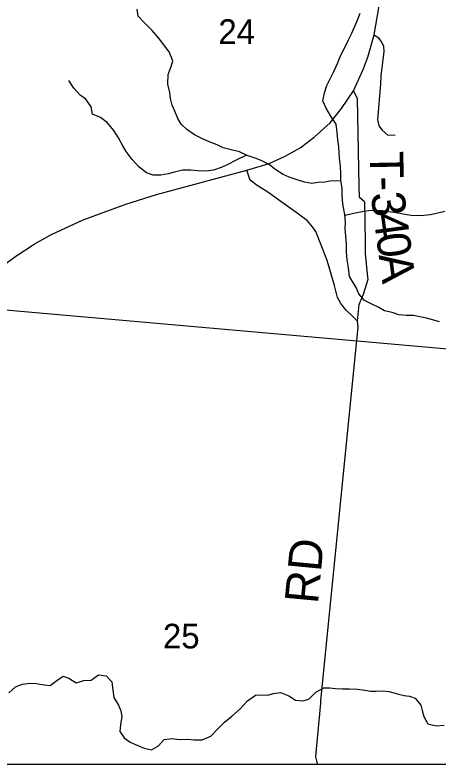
# Model space of a CAD drawing. Extents: x 0 to 42, y 0 to 22.
# Drawn here: x 4.427 to 4.786, y 14.1 to 14.736 of the extents above; entities that cross this region are included whole.
import ezdxf

# ---------------------------------------------------------------- set-up
doc = ezdxf.new("R2010")
doc.units = 0
for name, color, linetype in [('GM_X_Major_River', 7, 'Continuous'), ('GM_X_Minor_River', 7, 'Continuous'), ('GM_X_Section', 7, 'Continuous'), ('GM_X_Section_Text', 7, 'Continuous'), ('GM_X_State_Route', 7, 'Continuous'), ('GM_X_Township_Road', 7, 'Continuous'), ('GM_X_Township_Road_Text', 7, 'Continuous'), ('GM_X_Unincorporated', 7, 'Continuous'), ('SH_Cut_Line', 7, 'Continuous'), ('SH_Data', 7, 'Continuous')]:
    doc.layers.add(name, color=color, linetype=linetype)

msp = doc.modelspace()

# ---------------------------------------------------------------- linework, layer by layer
at = {"layer": 'GM_X_Major_River'}
msp.add_lwpolyline([(4.42158, 14.16044), (4.42726, 14.16538), (4.43333, 14.16766), (4.43996, 14.16861), (4.44489, 14.16842), (4.4519, 14.1671), (4.45683, 14.16653), (4.46251, 14.1709), (4.46782, 14.17451), (4.47256, 14.17281), (4.47882, 14.16883), (4.48545, 14.17092), (4.49151, 14.17111), (4.49777, 14.17567), (4.5044, 14.17473), (4.50914, 14.1698), (4.5099, 14.16278), (4.51086, 14.15652), (4.51484, 14.14988), (4.51674, 14.14514), (4.5175, 14.14039), (4.51656, 14.13337), (4.51599, 14.12749), (4.51959, 14.12218), (4.52471, 14.11858), (4.53116, 14.11574), (4.53647, 14.11346), (4.54272, 14.11214), (4.54879, 14.11556), (4.55352, 14.12069), (4.56035, 14.12164), (4.56622, 14.12069), (4.57324, 14.12108), (4.57892, 14.12051), (4.58575, 14.12052), (4.59314, 14.12375), (4.59882, 14.12945), (4.60469, 14.13552), (4.61075, 14.14027), (4.61795, 14.14691), (4.62439, 14.15375), (4.63121, 14.1585), (4.63633, 14.15869), (4.64145, 14.15831), (4.64619, 14.15984), (4.65244, 14.16079), (4.65946, 14.15776), (4.66514, 14.15416), (4.67121, 14.15359), (4.67633, 14.15512), (4.68239, 14.161), (4.68921, 14.1648), (4.69414, 14.16461), (4.69888, 14.16405), (4.70494, 14.16386), (4.71082, 14.16368), (4.71764, 14.16349), (4.7239, 14.16274), (4.72883, 14.16179), (4.73356, 14.1618), (4.73868, 14.16199), (4.74475, 14.16143), (4.75252, 14.15935), (4.75726, 14.15821), (4.762, 14.15765), (4.76674, 14.15594), (4.77148, 14.15006), (4.77262, 14.14532), (4.77414, 14.14039), (4.77755, 14.13413), (4.78475, 14.13243), (4.7912, 14.133)], dxfattribs=at)
at = {"layer": 'GM_X_Minor_River'}
for points in [[(4.70371, 14.59465), (4.69549, 14.59484), (4.69019, 14.59391), (4.68433, 14.59356), (4.67885, 14.59283), (4.67281, 14.5938), (4.66639, 14.59591), (4.65979, 14.59803), (4.6547, 14.60033), (4.64753, 14.60491), (4.64264, 14.60872), (4.63604, 14.61216), (4.63094, 14.61408), (4.62415, 14.61638), (4.61755, 14.61964), (4.61057, 14.62137), (4.60377, 14.62311), (4.59849, 14.6256), (4.59189, 14.62809), (4.58548, 14.63077), (4.57925, 14.63402), (4.57285, 14.63841), (4.56796, 14.64317), (4.56514, 14.64792), (4.56271, 14.654), (4.56028, 14.65913), (4.55879, 14.66482), (4.55843, 14.66994), (4.55657, 14.67696), (4.5568, 14.68511), (4.55947, 14.69192), (4.56082, 14.69684), (4.55783, 14.70444), (4.55407, 14.70938), (4.54862, 14.71623), (4.54335, 14.7227), (4.53677, 14.72917), (4.5315, 14.73469), (4.53058, 14.74076)], [(4.71083, 14.5139), (4.7101, 14.52104), (4.70899, 14.52806), (4.70827, 14.53451), (4.7083, 14.54133), (4.70776, 14.54778), (4.70722, 14.5546), (4.70743, 14.55991), (4.70708, 14.56635), (4.7056, 14.57375), (4.70506, 14.57868), (4.7047, 14.5838), (4.70472, 14.58873), (4.70362, 14.59518), (4.70345, 14.60124), (4.70329, 14.60731), (4.70256, 14.61414), (4.70221, 14.61888), (4.70185, 14.62381), (4.70112, 14.62969), (4.70058, 14.63613), (4.69948, 14.64315), (4.69497, 14.64999), (4.69103, 14.65665), (4.68841, 14.66291), (4.68958, 14.66954), (4.69168, 14.67598), (4.69511, 14.68259), (4.69759, 14.68789), (4.70102, 14.69508), (4.70313, 14.70056), (4.70694, 14.70813), (4.70999, 14.71456), (4.71285, 14.72042), (4.71743, 14.73064), (4.71991, 14.73726)], [(4.62354, 14.61669), (4.61469, 14.61264), (4.60711, 14.60869), (4.60181, 14.60625), (4.59538, 14.604), (4.58895, 14.60309), (4.58215, 14.6035), (4.57629, 14.6039), (4.56911, 14.60393), (4.5623, 14.60226), (4.55681, 14.60096), (4.55076, 14.59985), (4.54415, 14.59969), (4.53849, 14.6018), (4.53208, 14.60675), (4.52644, 14.61322), (4.52137, 14.61988), (4.51855, 14.62482), (4.5148, 14.63147), (4.51067, 14.63775), (4.50541, 14.64421), (4.49938, 14.64879), (4.49259, 14.65147), (4.49167, 14.65792), (4.48698, 14.6642), (4.48208, 14.66763), (4.47681, 14.67372), (4.47268, 14.68018)], [(4.70711, 14.5659), (4.71313, 14.56727), (4.72032, 14.56876), (4.72713, 14.56968), (4.73393, 14.57003), (4.73884, 14.56981), (4.74432, 14.56884), (4.75055, 14.56806), (4.7564, 14.56689), (4.7632, 14.56591), (4.76906, 14.56551), (4.77416, 14.56587), (4.77983, 14.56641), (4.78607, 14.5679), (4.79175, 14.5692)], [(4.78741, 14.47527), (4.78267, 14.4766), (4.77622, 14.47849), (4.77053, 14.47962), (4.76523, 14.48076), (4.75935, 14.48075), (4.75291, 14.48113), (4.74722, 14.48321), (4.74059, 14.48472), (4.73585, 14.48738), (4.72997, 14.49022), (4.72371, 14.49344), (4.71878, 14.49894), (4.71669, 14.50444), (4.71083, 14.5139)]]:
    msp.add_lwpolyline(points, dxfattribs=at)
at = {"layer": 'GM_X_Section'}
msp.add_lwpolyline([(4.39069, 15.00589), (4.8862, 14.96502), (4.86634, 14.74322), (4.83953, 14.44809), (4.34454, 14.49165)], close=True, dxfattribs=at)
at = {"layer": 'GM_X_State_Route'}
for points in [[(4.45857, 14.54977), (4.48467, 14.56201), (4.52086, 14.5751), (4.54702, 14.58338), (4.6237, 14.60399), (4.6428, 14.60969), (4.65619, 14.61582), (4.66902, 14.62309), (4.68085, 14.63193), (4.69446, 14.64428), (4.70408, 14.65648), (4.71426, 14.6714), (4.72244, 14.68934), (4.7266, 14.69997), (4.73198, 14.71897), (4.73608, 14.74338)], [(4.37582, 14.49421), (4.41709, 14.52353), (4.42756, 14.53105), (4.44325, 14.54108), (4.45677, 14.54893), (4.45857, 14.54977)]]:
    msp.add_lwpolyline(points, dxfattribs=at)
at = {"layer": 'GM_X_Township_Road'}
for points in [[(2.1, 16.7767), (2.1, 14.1), (4.80642, 14.1), (4.86241, 14.74155), (4.87577, 14.903), (4.88082, 14.9641), (4.90774, 15.22465), (4.90782, 15.22542), (4.91025, 15.24876), (4.91234, 15.26666), (4.91693, 15.30071), (4.92061, 15.33827), (4.92229, 15.35537), (4.9225, 15.35759), (4.92364, 15.36537), (4.92223, 15.37611), (4.92602, 15.41635), (4.9302, 15.46506), (4.93268, 15.49943), (4.95383, 15.74551), (4.96357, 15.8483), (4.97611, 15.98164)], [(4.73198, 14.71897), (4.73526, 14.71658), (4.73809, 14.71256), (4.73973, 14.70943), (4.74003, 14.70451), (4.73765, 14.68438), (4.73736, 14.677), (4.73478, 14.64715), (4.73578, 14.6417), (4.73866, 14.63811), (4.7436, 14.63368), (4.74969, 14.63397)], [(4.72446, 14.54285), (4.72395, 14.57675), (4.71936, 14.58077), (4.71907, 14.59053), (4.71771, 14.66495), (4.71426, 14.6714)], [(4.68671, 14.15365), (4.71815, 14.47114), (4.71768, 14.47588), (4.714, 14.47968), (4.70789, 14.4855), (4.70368, 14.49072), (4.70083, 14.49606), (4.69822, 14.50624), (4.69185, 14.52725), (4.68672, 14.54134), (4.68236, 14.55195), (4.67945, 14.55598), (4.67532, 14.56112), (4.66774, 14.56664), (4.64151, 14.58546), (4.63239, 14.59088), (4.62655, 14.59544), (4.6237, 14.60399)], [(4.7257, 14.52199), (4.72465, 14.53296), (4.72461, 14.53346), (4.72446, 14.54285)], [(4.71768, 14.47588), (4.7191, 14.48995), (4.72271, 14.49871), (4.72669, 14.51162), (4.72655, 14.51311), (4.7257, 14.52199)], [(4.68379, 14.1), (4.68313, 14.10278), (4.68233, 14.10613), (4.68292, 14.1125), (4.68652, 14.1517), (4.68671, 14.15365)]]:
    msp.add_lwpolyline(points, dxfattribs=at)
at = {"layer": 'GM_X_Unincorporated'}
msp.add_lwpolyline([(4.30879, 14.1), (4.80872, 14.1), (4.82178, 14.24637), (4.83953, 14.44809), (4.34454, 14.49165)], close=True, dxfattribs=at)
at = {"layer": 'SH_Cut_Line'}
msp.add_lwpolyline([(2.1, 20.9), (2.1, 14.1), (8.05023, 14.1), (8.06868, 14.30702), (8.08338, 14.51358), (8.1512, 15.24132), (8.15761, 15.31908), (8.1628, 15.37905), (8.16837, 15.44612), (8.16945, 15.45935), (8.16983, 15.46634), (8.17227, 15.49063), (8.24231, 16.32059)], dxfattribs=at)
at = {"layer": 'SH_Data'}
msp.add_line((2.1, 14.1), (8.9, 14.1), dxfattribs=at)

# ---------------------------------------------------------------- texts
at = {"layer": 'GM_X_Section_Text'}
for s, p in [('24', (4.5996, 14.71117)), ('25', (4.55251, 14.1981))]:
    msp.add_text(s, height=0.020928, rotation=0.00001, dxfattribs=at).set_placement(p)
at = {"layer": 'GM_X_Township_Road_Text'}
for s, height, rotation, p in [('T', 0.02841, 271.06296, (4.72819, 14.61994)), ('-', 0.02841, 271.24778, (4.72859, 14.59863)), ('3', 0.02841, 276.41468, (4.72903, 14.58428)), ('4', 0.02841, 277.64506, (4.73105, 14.56637)), ('0', 0.02841, 277.65956, (4.73336, 14.54915)), ('A', 0.02841, 277.6638, (4.73567, 14.53195)), ('RD', 0.028409, 84.58411, (4.6841, 14.23537))]:
    msp.add_text(s, height=height, rotation=rotation, dxfattribs=at).set_placement(p)

doc.saveas('drawing.dxf')
